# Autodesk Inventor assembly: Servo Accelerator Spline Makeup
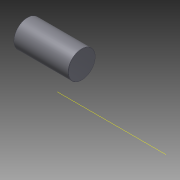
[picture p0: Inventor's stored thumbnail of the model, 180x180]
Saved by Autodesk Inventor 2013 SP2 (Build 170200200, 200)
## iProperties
Created: 2020-02
Part Number: Servo Accelerator Spline Makeup
Document SubType Name: Assembly
Designer: DELL
Author: DELL
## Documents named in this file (3)
- C:\Users\DELL\Dropbox\Inventor\Projects\Quadcopter F450\STL Files\Servo Accelerator Spline Makeup.iam
- C:\Users\DELL\Dropbox\Inventor\Projects\Quadcopter F450\STL Files\Servo Accelerator Spline Makeup\Design Accelerator\Shaft1.iam
- C:\Users\DELL\Dropbox\Inventor\Projects\Quadcopter F450\STL Files\Servo Accelerator Spline Makeup\Design Accelerator\Involute Spline Connection1.iam
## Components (2 placed, 2 different names)
1. Shaft:1 [sub-assembly]
2. Involute Spline Connection:1 [sub-assembly]
